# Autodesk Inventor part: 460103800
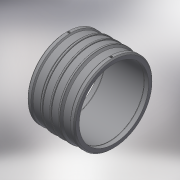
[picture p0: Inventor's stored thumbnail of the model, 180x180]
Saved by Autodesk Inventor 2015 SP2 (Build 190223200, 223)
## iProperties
Created: 2017-06
Part Number: 460103800
Material: Generic
Description: PLASSON LIGHTFIT COUPLER 800
Document SubType Name: Modeling
Designer: KIM
Mass: 59719.1 g
Surface Area: 30406.1 cm^2
Volume: 59719.1 cm^3
Density: 1 g/cm^3
Appearance: Default
Author: KIM
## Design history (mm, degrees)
derived "460103.ipt"
feature "Solid1::460103.ipt"
tag "TaggingFeature1"
body "Solid1"
other parameters: "d14" = 17.6296, "d19" = 3.52592, "d20" = 168 deg, "d23" = 913, "d24" = 873, "d25" = 135 deg, "d27" = 135 deg, "d35" = 15, "d39" = 0, "d40" = 4, "d41" = 14, "d42" = 0, "d43" = 135 deg, "d44" = 55, "d48" = 894.74, "d49" = 913, "d50" = 4.565, "d51" = 6, "d52" = 0, "D_" = 913, "d_2" = 12
